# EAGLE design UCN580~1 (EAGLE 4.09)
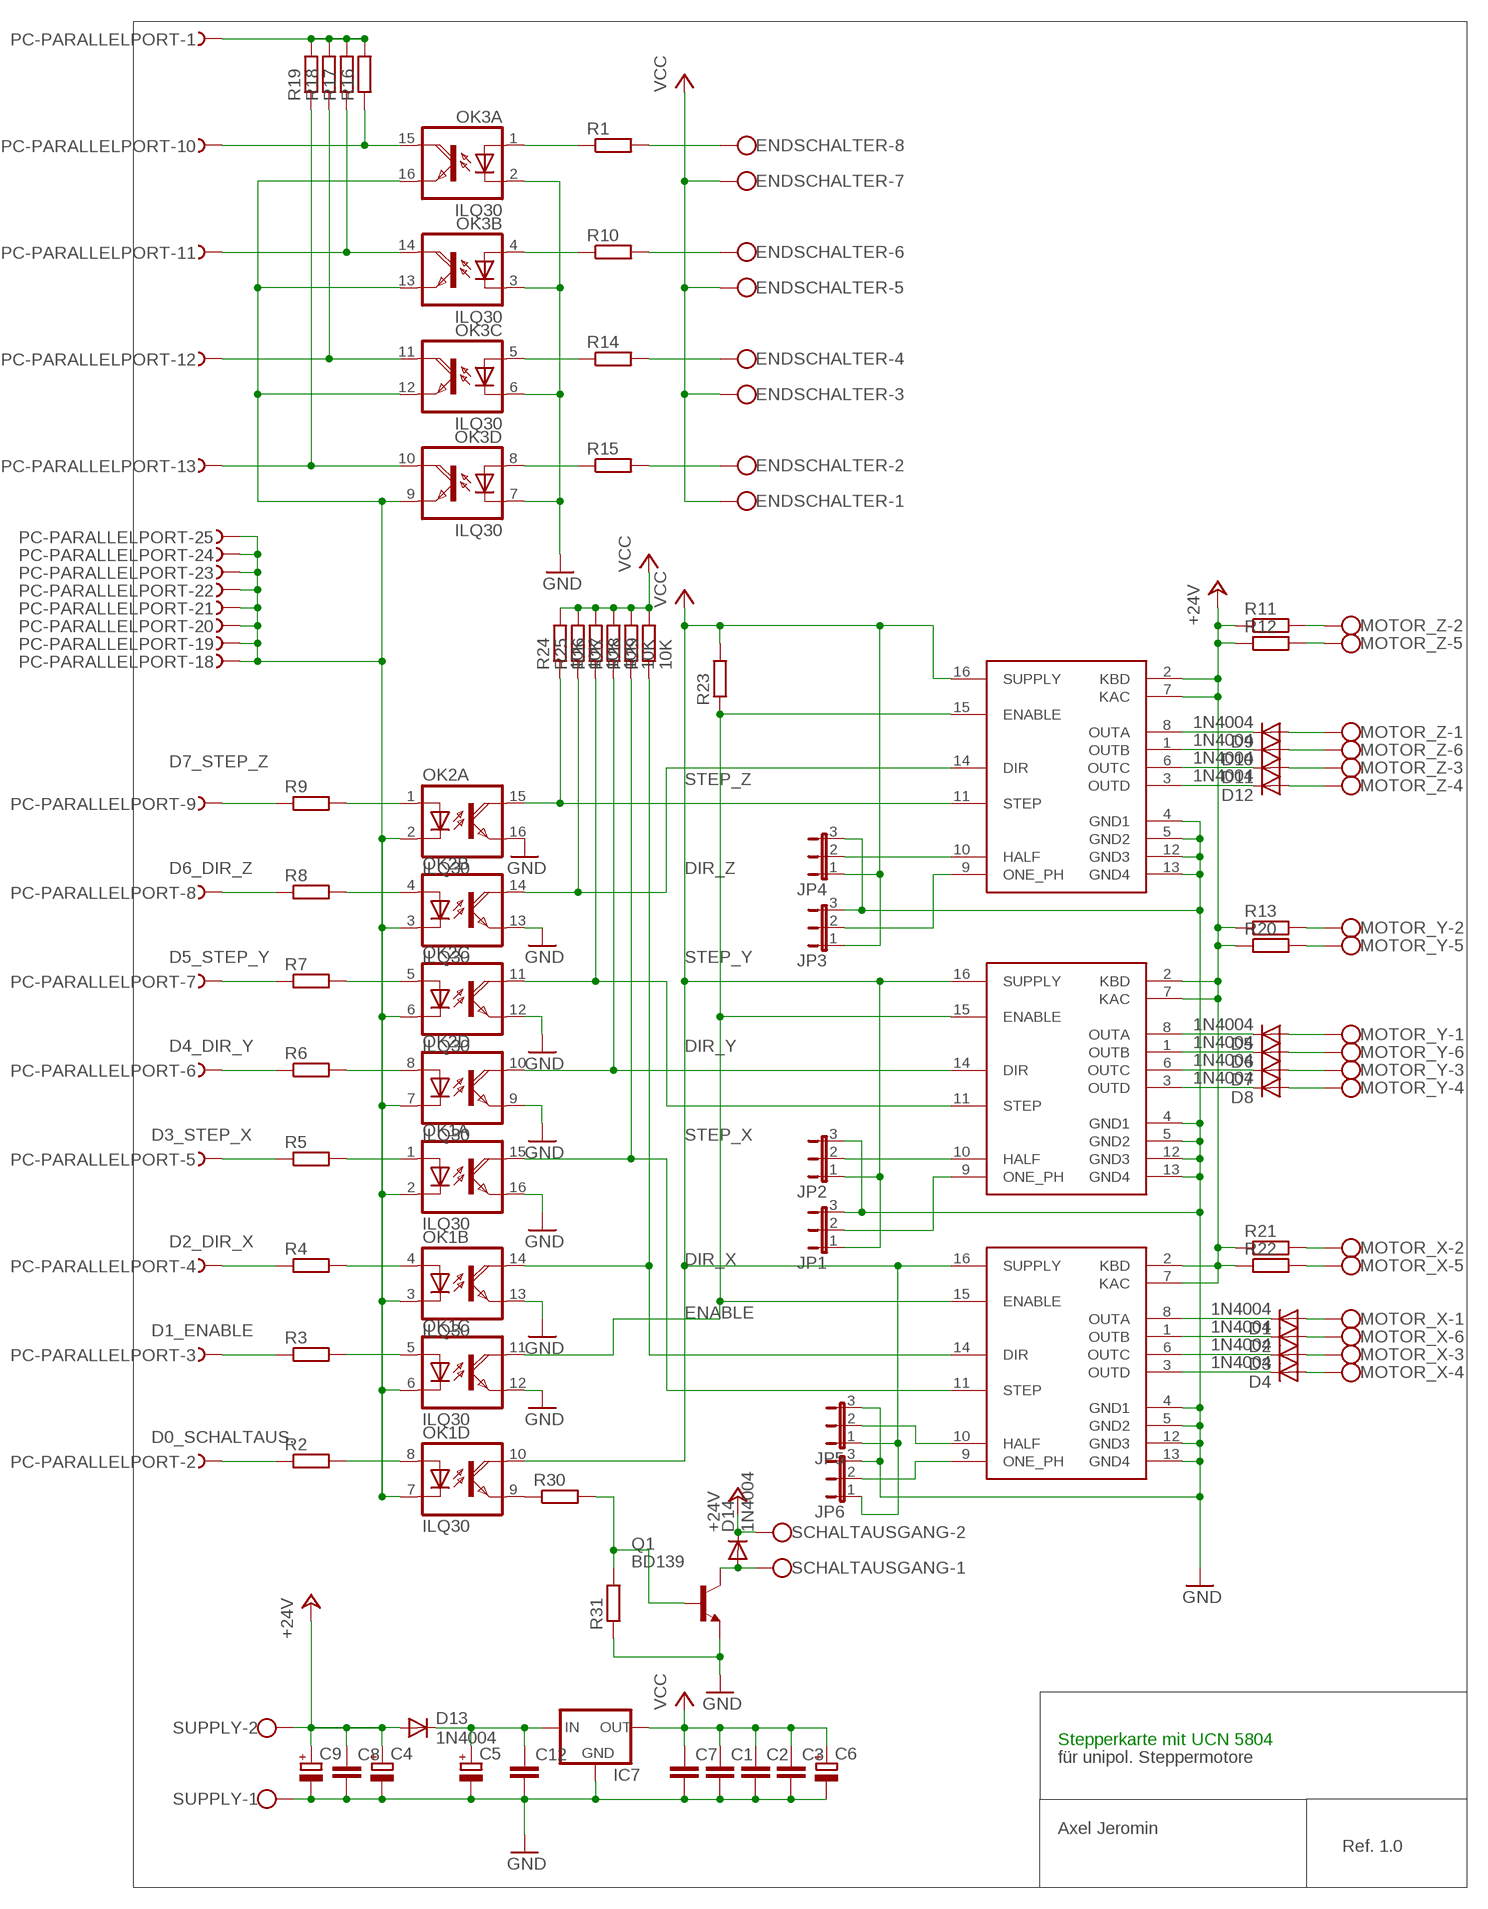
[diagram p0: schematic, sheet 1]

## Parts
C1  C-EU050-025X075  [C050-025X075]
C2  C-EU050-025X075  [C050-025X075]
C3  C-EU050-025X075  [C050-025X075]
C4  CPOL-EUE5-10.5  [E5-10,5]
C5  CPOL-EUE5-10.5  [E5-10,5]
C6  CPOL-EUE5-8.5  [E5-8,5]
C7  C-EU025-030X050  [C025-030X050]
C8  C-EU050-025X075  [C050-025X075]
C9  CPOL-EUE5-8.5  [E5-8,5]
C12  C-EU025-030X050  [C025-030X050]
D1  1N4004  [DO41-10]
D2  1N4004  [DO41-10]
D3  1N4004  [DO41-10]
D4  1N4004  [DO41-10]
D5  1N4004  [DO41-10]
D6  1N4004  [DO41-10]
D7  1N4004  [DO41-10]
D8  1N4004  [DO41-10]
D9  1N4004  [DO41-10]
D10  1N4004  [DO41-10]
D11  1N4004  [DO41-10]
D12  1N4004  [DO41-10]
D13  1N4004  [DO41-10]
D14  1N4004  [DO41-10]
ENDSCHALTER  AK300/8  [AK300/8]
IC7  78XXS  [78XXS]
JP1  JP2E  [JP2]
JP2  JP2E  [JP2]
JP3  JP2E  [JP2]
JP4  JP2E  [JP2]
JP5  JP2E  [JP2]
JP6  JP2E  [JP2]
MOTOR_X  AK300/6  [AK300/6]
MOTOR_Y  AK300/6  [AK300/6]
MOTOR_Z  AK300/6  [AK300/6]
OK1  ILQ30  [DIL16]
OK2  ILQ30  [DIL16]
OK3  ILQ30  [DIL16]
PC-PARALLELPORT  F25HS  [F25H]
Q1  BD139  [TO126]
R1  R-EU_0207/2V  [0207/2V]
R2  R-EU_0204/7  [0204/7]
R3  R-EU_0204/7  [0204/7]
R4  R-EU_0204/7  [0204/7]
R5  R-EU_0204/7  [0204/7]
R6  R-EU_0204/7  [0204/7]
R7  R-EU_0204/5  [0204/5]
R8  R-EU_0204/5  [0204/5]
R9  R-EU_0204/5  [0204/5]
R10  R-EU_0207/2V  [0207/2V]
R11  R-EU_0414/15  [0414/15]
R12  R-EU_0414/15  [0414/15]
R13  R-EU_0414/15  [0414/15]
R14  R-EU_0207/2V  [0207/2V]
R15  R-EU_0207/2V  [0207/2V]
R16  R-EU_0207/15  [0207/15]
R17  R-EU_0207/12  [0207/12]
R18  R-EU_0204/7  [0204/7]
R19  R-EU_0204/5  [0204/5]
R20  R-EU_0414/15  [0414/15]
R21  R-EU_0414/15  [0414/15]
R22  R-EU_0414/15  [0414/15]
R23  R-EU_0204/5  [0204/5]
R24  10K  R-EU_0207/10  [0207/10]
R25  10K  R-EU_0204/7  [0204/7]
R26  10K  R-EU_0207/10  [0207/10]
R27  10K  R-EU_0204/7  [0204/7]
R28  10K  R-EU_0204/7  [0204/7]
R29  10K  R-EU_0204/5  [0204/5]
R30  R-EU_0204/7  [0204/7]
R31  R-EU_0204/5  [0204/5]
SCHALTAUSGANG  AK300/2  [AK300/2]
SUPPLY  AK300/2  [AK300/2]
X-ACHSE  UCN5804  [DIL16]
Y-ACHSE  UCN5804  [DIL16]
Z-ACHSE  UCN5804  [DIL16]

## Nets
+24V: C4.+ C8.1 C9.+ D13.A D14.C R11.1 R12.1 R13.1 R20.1 R21.1 R22.1 SCHALTAUSGANG.2 SUPPLY.2 X-ACHSE.2(KBD) X-ACHSE.7(KAC) Y-ACHSE.2(KBD) Y-ACHSE.7(KAC) Z-ACHSE.2(KBD) Z-ACHSE.7(KAC)
D0_SCHALTAUS.: PC-PARALLELPORT.2 R2.1
D1_ENABLE: PC-PARALLELPORT.3 R3.1
D2_DIR_X: PC-PARALLELPORT.4 R4.1
D3_STEP_X: PC-PARALLELPORT.5 R5.1
D4_DIR_Y: PC-PARALLELPORT.6 R6.1
D5_STEP_Y: PC-PARALLELPORT.7 R7.1
D6_DIR_Z: PC-PARALLELPORT.8 R8.1
D7_STEP_Z: PC-PARALLELPORT.9 R9.1
DIR_X: OK1.14(B:COL) R29.1 X-ACHSE.14(DIR)
DIR_Y: OK2.10(D:COL) R27.1 Y-ACHSE.14(DIR)
DIR_Z: OK2.14(B:COL) R25.1 Z-ACHSE.14(DIR)
ENABLE: OK1.11(C:COL) R23.1 X-ACHSE.15(ENABLE) Y-ACHSE.15(ENABLE) Z-ACHSE.15(ENABLE)
GND: C1.2 C2.2 C3.2 C4.- C5.- C6.- C7.2 C8.2 C9.- C12.2 IC7.GND JP1.3 JP2.3 JP3.3 JP4.3 JP5.3 JP6.3 OK1.12(C:EMI) OK1.13(B:EMI) OK1.16(A:EMI) OK2.9(D:EMI) OK2.12(C:EMI) OK2.13(B:EMI) OK2.16(A:EMI) OK3.2(A:C) OK3.3(B:C) OK3.6(C:C) OK3.7(D:C) Q1.1(E) R31.1 SUPPLY.1 X-ACHSE.4(GND1) X-ACHSE.5(GND2) X-ACHSE.12(GND3) X-ACHSE.13(GND4) Y-ACHSE.4(GND1) Y-ACHSE.5(GND2) Y-ACHSE.12(GND3) Y-ACHSE.13(GND4) Z-ACHSE.4(GND1) Z-ACHSE.5(GND2) Z-ACHSE.12(GND3) Z-ACHSE.13(GND4)
LIMIT_1: OK3.10(D:COL) PC-PARALLELPORT.13 R19.1
LIMIT_2: OK3.11(C:COL) PC-PARALLELPORT.12 R18.1
LIMIT_3: OK3.14(B:COL) PC-PARALLELPORT.11 R17.1
LIMIT_4: OK3.15(A:COL) PC-PARALLELPORT.10 R16.1
N$1: OK1.2(A:C) OK1.3(B:C) OK1.6(C:C) OK1.7(D:C) OK2.2(A:C) OK2.3(B:C) OK2.6(C:C) OK2.7(D:C) OK3.9(D:EMI) OK3.12(C:EMI) OK3.13(B:EMI) OK3.16(A:EMI) PC-PARALLELPORT.18 PC-PARALLELPORT.19 PC-PARALLELPORT.20 PC-PARALLELPORT.21 PC-PARALLELPORT.22 PC-PARALLELPORT.23 PC-PARALLELPORT.24 PC-PARALLELPORT.25
N$2: C5.+ C12.1 D13.C IC7.IN
N$3: D9.C Z-ACHSE.8(OUTA)
N$4: D10.C Z-ACHSE.1(OUTB)
N$5: OK2.4(B:A) R8.2
N$6: OK1.8(D:A) R2.2
N$7: OK1.5(C:A) R3.2
N$8: D11.C Z-ACHSE.6(OUTC)
N$9: D12.C Z-ACHSE.3(OUTD)
N$10: PC-PARALLELPORT.1 R16.2 R17.2 R18.2 R19.2
N$11: D5.C Y-ACHSE.8(OUTA)
N$12: D6.C Y-ACHSE.1(OUTB)
N$13: OK2.1(A:A) R9.2
N$14: OK1.4(B:A) R4.2
N$15: OK1.1(A:A) R5.2
N$16: OK2.8(D:A) R6.2
N$17: OK2.5(C:A) R7.2
N$18: D7.C Y-ACHSE.6(OUTC)
N$19: D8.C Y-ACHSE.3(OUTD)
N$20: D1.C X-ACHSE.8(OUTA)
N$21: D2.C X-ACHSE.1(OUTB)
N$22: D3.C X-ACHSE.6(OUTC)
N$23: D4.C X-ACHSE.3(OUTD)
N$24: MOTOR_Z.2 R11.2
N$25: MOTOR_Z.5 R12.2
N$26: MOTOR_X.5 R22.2
N$27: D1.A MOTOR_X.1
N$28: MOTOR_Y.2 R13.2
N$29: MOTOR_Y.5 R20.2
N$30: D2.A MOTOR_X.6
N$31: D3.A MOTOR_X.3
N$32: D4.A MOTOR_X.4
N$33: D5.A MOTOR_Y.1
N$34: MOTOR_X.2 R21.2
N$35: OK3.1(A:A) R1.1
N$36: D6.A MOTOR_Y.6
N$37: OK3.4(B:A) R10.1
N$38: D7.A MOTOR_Y.3
N$39: ENDSCHALTER.8 R1.2
N$40: ENDSCHALTER.6 R10.2
N$41: ENDSCHALTER.4 R14.2
N$42: ENDSCHALTER.2 R15.2
N$43: OK3.5(C:A) R14.1
N$44: D8.A MOTOR_Y.4
N$45: OK3.8(D:A) R15.1
N$46: D9.A MOTOR_Z.1
N$47: D10.A MOTOR_Z.6
N$48: D11.A MOTOR_Z.3
N$49: D12.A MOTOR_Z.4
N$50: OK1.9(D:EMI) R30.1
N$51: JP6.2 X-ACHSE.9(ONE_PH)
N$52: JP5.2 X-ACHSE.10(HALF)
N$53: JP1.2 Y-ACHSE.9(ONE_PH)
N$54: JP2.2 Y-ACHSE.10(HALF)
N$55: JP3.2 Z-ACHSE.9(ONE_PH)
N$56: JP4.2 Z-ACHSE.10(HALF)
N$57: Q1.3(B) R30.2 R31.2
N$58: D14.A Q1.2(C) SCHALTAUSGANG.1
STEP_X: OK1.15(A:COL) R28.1 X-ACHSE.11(STEP)
STEP_Y: OK2.11(C:COL) R26.1 Y-ACHSE.11(STEP)
STEP_Z: OK2.15(A:COL) R24.1 Z-ACHSE.11(STEP)
VCC: C1.1 C2.1 C3.1 C6.+ C7.1 ENDSCHALTER.1 ENDSCHALTER.3 ENDSCHALTER.5 ENDSCHALTER.7 IC7.OUT JP1.1 JP2.1 JP3.1 JP4.1 JP5.1 JP6.1 OK1.10(D:COL) R23.2 R24.2 R25.2 R26.2 R27.2 R28.2 R29.2 X-ACHSE.16(SUPPLY) Y-ACHSE.16(SUPPLY) Z-ACHSE.16(SUPPLY)
Unconnected: PC-PARALLELPORT.14 PC-PARALLELPORT.15 PC-PARALLELPORT.16 PC-PARALLELPORT.17

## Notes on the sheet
- Stepperkarte mit UCN 5804
- für unipol. Steppermotore
- Axel Jeromin
- Ref. 1.0

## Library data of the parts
C1-C3 C7 C8 C12 = rcl:C-EU: CAPACITOR, European symbol
C4-C6 C9 = rcl:CPOL-EU: POLARIZED CAPACITOR, European symbol
D1-D14 = diode:1N4004: DIODE
ENDSCHALTER = con-ptr500:AK300/8: CONNECTOR
IC7 = v-reg:78XXS: VOLTAGE REGULATOR
JP1-JP6 = jumper:JP2E: JUMPER
MOTOR_X MOTOR_Y MOTOR_Z = con-ptr500:AK300/6: CONNECTOR
OK1-OK3 = optocoupler:ILQ30: SIEMENS OPTO COUPLER
PC-PARALLELPORT = con-subd:F25?S: SUB-D
Q1 = transistor-npn:BD139*: NPN Transistor
R1-R31 = rcl:R-EU_: RESISTOR, European symbol
SCHALTAUSGANG SUPPLY = con-ptr500:AK300/2: CONNECTOR
X-ACHSE Y-ACHSE Z-ACHSE = uln-udn:UCN5804: Stepper

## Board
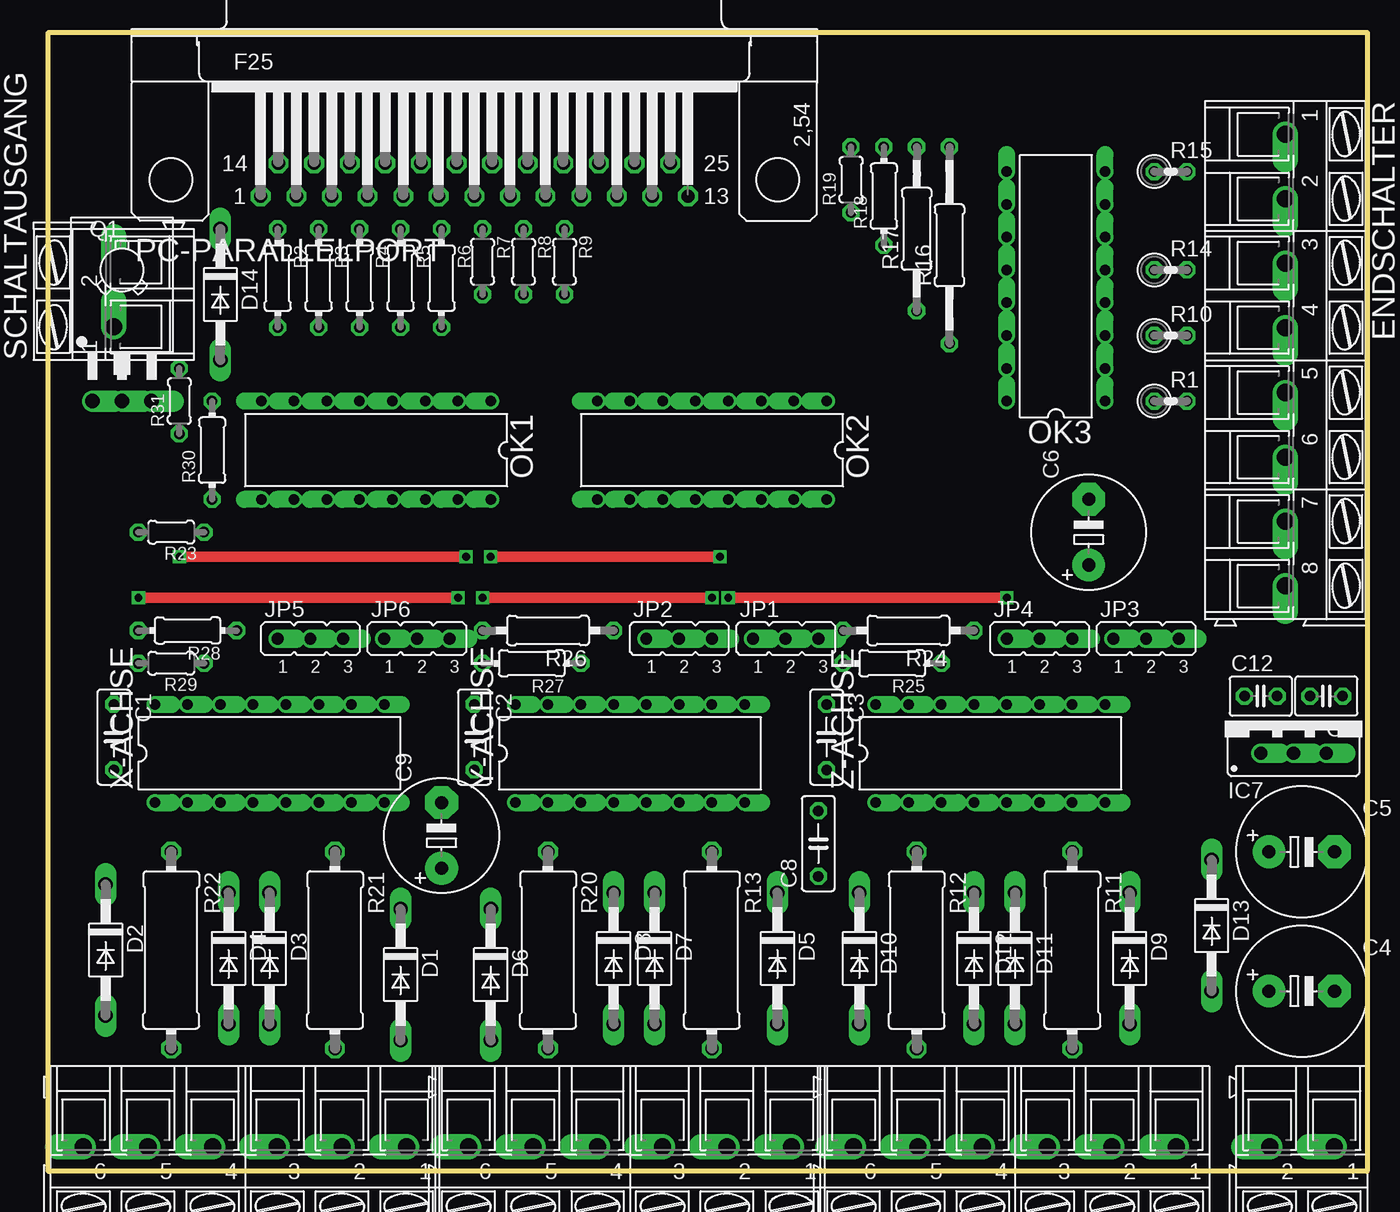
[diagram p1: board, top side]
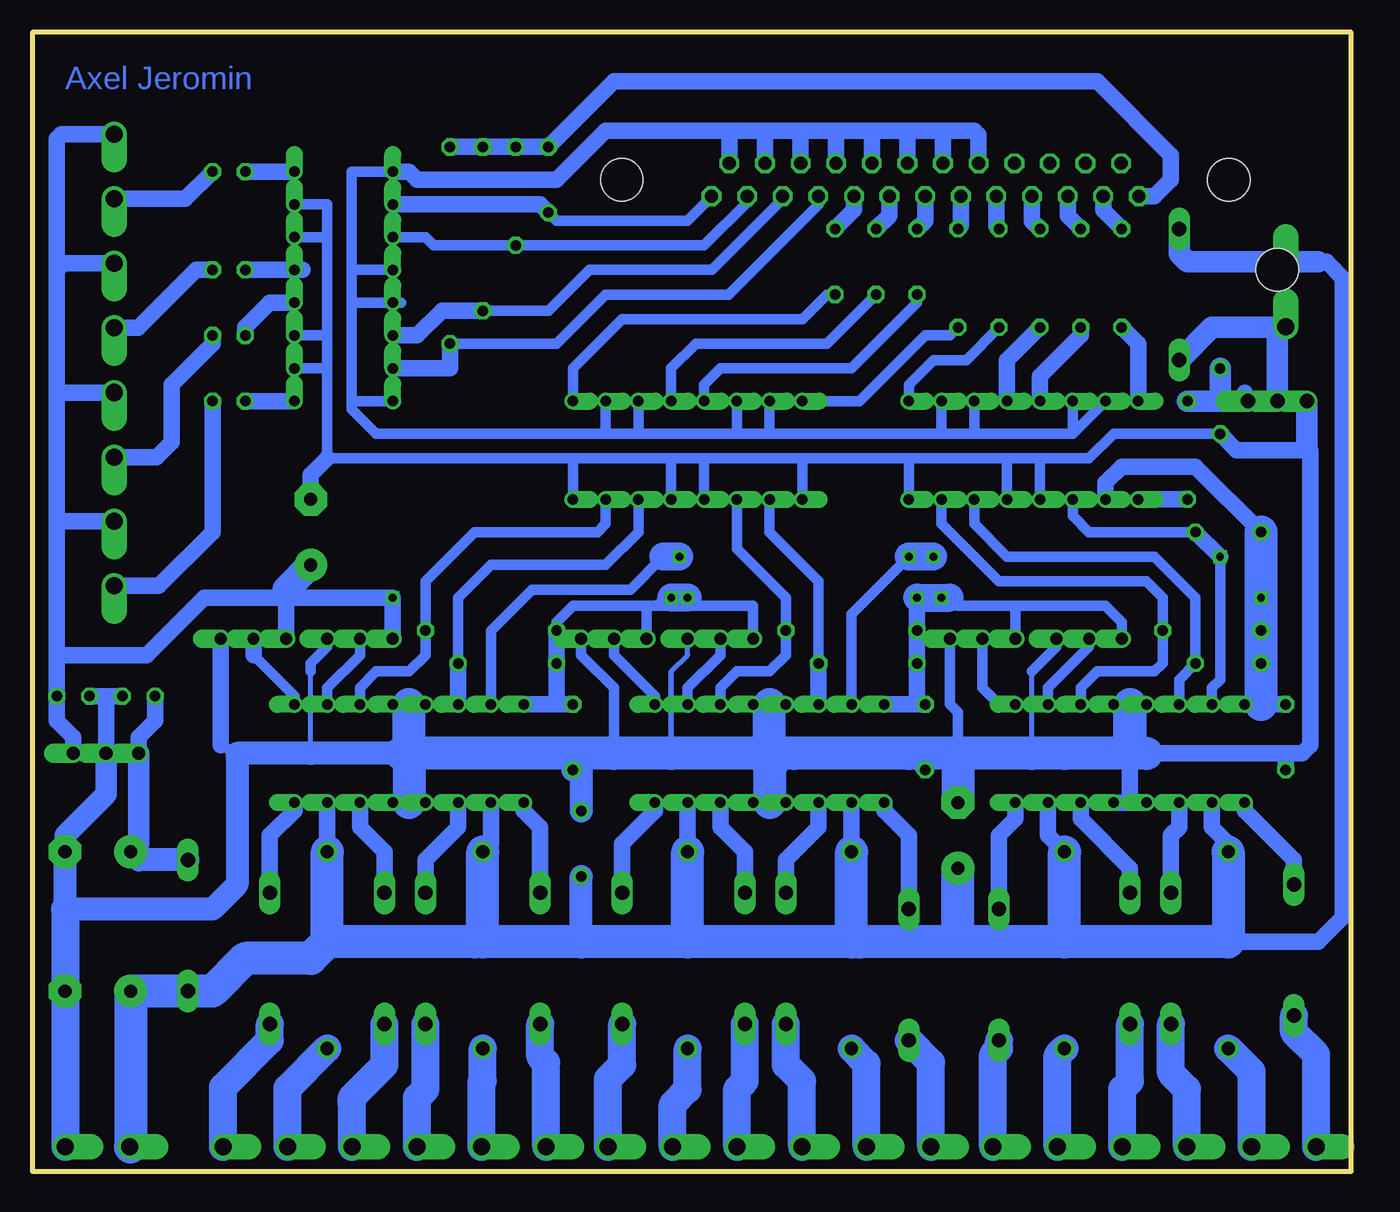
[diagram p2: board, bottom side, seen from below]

Size 102.23 x 88.27 mm. Coordinates in mm from the lower left corner, seen from the top.
Outline: 0,0 0,88.27 102.23,88.27 102.23,0 0,0
Copper layers used: Top, Bottom

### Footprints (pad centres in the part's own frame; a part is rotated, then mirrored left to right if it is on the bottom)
C050-025X075 = drill 0.813 octagon: 1 -2.54,0; 2 2.54,0
E5-10,5 = drill 1.016 pad 2.54 round: + -2.54,0 | drill 1.016 pad 2.54 octagon: - 2.54,0
E5-8,5 = drill 1.016 pad 2.54 round: + -2.54,0 | drill 1.016 pad 2.54 octagon: - 2.54,0
C025-030X050 = drill 0.813 octagon: 1 -1.27,0; 2 1.27,0
DO41-10 = drill 1.118 long: A 5.08,0; C -5.08,0
AK300/8 = drill 1.321 offset: 1 -17.501,0; 2 -12.497,0; 3 -7.518,0; 4 -2.515,0; 5 2.515,0; 6 7.518,0; 7 12.497,0; 8 17.501,0
78XXS = drill 1.016 offset: GND 0,-2.54; IN -2.54,-2.54; OUT 2.54,-2.54
JP2 = drill 0.914 offset: 1 -2.54,0; 2 0,0; 3 2.54,0
AK300/6 = drill 1.321 offset: 1 -12.522,0; 2 -7.518,0; 3 -2.515,0; 4 2.515,0; 5 7.518,0; 6 12.522,0
DIL16 = drill 0.813 offset: 1 -8.89,-3.81; 2 -6.35,-3.81; 3 -3.81,-3.81; 4 -1.27,-3.81; 5 1.27,-3.81; 6 3.81,-3.81; 7 6.35,-3.81; 8 8.89,-3.81; 9 8.89,3.81; 10 6.35,3.81; 11 3.81,3.81; 12 1.27,3.81; 13 -1.27,3.81; 14 -3.81,3.81; 15 -6.35,3.81; 16 -8.89,3.81
F25H = drill 1.016 octagon: 1 -16.561,-1.27; 2 -13.792,-1.27; 3 -11.049,-1.27; 4 -8.28,-1.27; 5 -5.512,-1.27; 6 -2.769,-1.27; 7 0,-1.27; 8 2.769,-1.27; 9 5.512,-1.27; 10 8.28,-1.27; 11 11.049,-1.27; 12 13.792,-1.27; 13 16.561,-1.27; 14 -15.189,1.27; 15 -12.421,1.27; 16 -9.652,1.27; 17 -6.909,1.27; 18 -4.14,1.27; 19 -1.372,1.27; 20 1.372,1.27; 21 4.14,1.27; 22 6.909,1.27; 23 9.652,1.27; 24 12.421,1.27; 25 15.189,1.27 | hole 3.302: -23.52,0; 23.52,0
TO126 = drill 1.118 offset: 1 -2.286,-5.08; 2 0,-5.08; 3 2.286,-5.08 | hole 3.302: 0,5.08
0207/2V = drill 0.813 octagon: 1 -1.27,0; 2 1.27,0
0204/7 = drill 0.813 octagon: 1 -3.81,0; 2 3.81,0
0204/5 = drill 0.813 octagon: 1 -2.54,0; 2 2.54,0
0414/15 = drill 1.016 octagon: 1 -7.62,0; 2 7.62,0
0207/15 = drill 0.813 octagon: 1 -7.62,0; 2 7.62,0
0207/12 = drill 0.813 octagon: 1 -6.35,0; 2 6.35,0
0207/10 = drill 0.813 octagon: 1 -5.08,0; 2 5.08,0
AK300/2 = drill 1.321 offset: 1 -2.515,0; 2 2.489,0

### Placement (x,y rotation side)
C1  5.08,33.66 270 top
C2  33.02,33.66 270 top
C3  60.32,33.66 270 top
C4  97.16,13.97 0 top
C5  97.16,24.77 0 top
C6  80.65,49.53 90 top
C7  99.06,36.83 180 top
C8  59.69,25.4 90 top
C9  30.48,26.04 90 top
C12  93.98,36.83 0 top
D1  27.31,15.24 270 top
D2  4.45,17.14 270 top
D3  17.15,16.51 270 top
D4  13.97,16.51 270 top
D5  56.52,16.51 270 top
D6  34.29,15.24 270 top
D7  46.99,16.51 270 top
D8  43.81,16.51 270 top
D9  83.82,16.51 270 top
D10  62.86,16.51 270 top
D11  74.93,16.51 270 top
D12  71.76,16.51 270 top
D13  90.17,19.05 270 top
D14  13.33,67.94 270 top
ENDSCHALTER  95.89,62.87 270 top
IC7  96.52,34.92 0 top
JP1  57.15,41.27 0 top
JP2  48.89,41.27 0 top
JP3  85.09,41.27 0 top
JP4  76.84,41.27 0 top
JP5  20.32,41.27 0 top
JP6  28.58,41.27 0 top
MOTOR_X  15.24,1.91 180 top
MOTOR_Y  45.09,1.91 180 top
MOTOR_Z  74.93,1.91 180 top
OK1  25.4,55.88 180 top
OK2  51.43,55.88 180 top
OK3  78.11,68.58 90 top
PC-PARALLELPORT  33.02,76.83 0 top
Q1  5.71,64.77 0 top
R1  87,59.69 0 top
R2  17.78,69.22 270 top
R3  20.96,69.22 270 top
R4  24.13,69.22 270 top
R5  27.31,69.22 270 top
R6  30.48,69.22 270 top
R7  33.66,70.48 270 top
R8  36.83,70.48 270 top
R9  40,70.48 270 top
R10  87,64.77 0 top
R11  79.38,17.14 270 top
R12  67.31,17.14 270 top
R13  51.43,17.14 270 top
R14  87,69.85 0 top
R15  87,77.47 0 top
R16  69.85,71.75 90 top
R17  67.31,73.03 90 top
R18  64.77,75.56 90 top
R19  62.23,76.83 90 top
R20  38.73,17.14 270 top
R21  22.23,17.14 270 top
R22  9.53,17.14 270 top
R23  9.53,49.53 180 top
R24  66.68,41.91 180 top
R25  65.41,39.37 180 top
R26  38.73,41.91 180 top
R27  37.46,39.37 180 top
R28  10.79,41.91 180 top
R29  9.53,39.37 180 top
R30  12.7,55.88 90 top
R31  10.16,59.69 90 top
SCHALTAUSGANG  5.08,67.94 90 top
SUPPLY  97.16,1.91 180 top
X-ACHSE  17.15,32.38 0 top
Y-ACHSE  45.09,32.38 0 top
Z-ACHSE  73.03,32.38 0 top

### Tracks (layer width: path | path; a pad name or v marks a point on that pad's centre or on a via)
+24V
  Bottom 0.305: 30.48,18.41 38.1,18.41 38.1,17.78 | SCHALTAUSGANG.2 2.59,70.43 2.54,70.48
  Bottom 0.813: 94.62,1.91 SUPPLY.2
  Bottom 1.27: Z-ACHSE.7 79.38,25.4 78.74,24.77 R11.1 | R20.1 Y-ACHSE.2 | R13.1 Y-ACHSE.7 | Z-ACHSE.2 66.68,25.4 R12.1 | 9.53,25.4 R22.1 | R21.1 23.5,26.04 X-ACHSE.7 | X-ACHSE.2 10.79,26.67 9.53,25.4 | 9.53,25.4 9.53,18.41 8.89,17.78 2.54,17.78 0.64,19.68 0.64,69.22 1.91,70.48 2.54,70.48
  Bottom 1.676: 2.54,70.48 12.7,70.48 13.33,71.12 D14.C
  Bottom 1.778: C8.1 59.69,17.78 67.95,17.78
  Bottom 2.184: C4.+ 94.67,13.92
  Bottom 2.54: 79.38,17.78 R11.1 | 22.23,17.78 9.53,17.78 R22.1 | 22.23,17.78 38.1,17.78 38.73,17.78 | 38.73,17.78 51.43,17.78 | 51.43,17.78 59.69,17.78 67.31,17.78 | 67.31,17.78 67.95,17.78 79.38,17.78 | 22.23,17.78 R21.1 | 38.73,17.78 R20.1 | 51.43,17.78 R13.1 | 67.31,17.78 R12.1 | 79.38,17.78 80.65,16.51 85.73,16.51 88.27,13.97 D13.A C4.+ 94.62,1.91 | 30.48,18.41 C9.+
D0_SCHALTAUS.
  Bottom 1.27: PC-PARALLELPORT.2 19.23,74.47 R2.1
D1_ENABLE
  Bottom 1.27: PC-PARALLELPORT.3 21.97,74.04 R3.1
D2_DIR_X
  Bottom 1.27: PC-PARALLELPORT.4 24.74,73.64 R4.1
D3_STEP_X
  Bottom 1.27: PC-PARALLELPORT.5 27.51,73.23 R5.1
D4_DIR_Y
  Bottom 1.27: PC-PARALLELPORT.6 30.25,73.25 R6.1
D5_STEP_Y
  Bottom 1.27: PC-PARALLELPORT.7 33.02,73.66 R7.1
D6_DIR_Z
  Bottom 1.27: PC-PARALLELPORT.8 35.79,74.07 R8.1
D7_STEP_Z
  Bottom 1.27: PC-PARALLELPORT.9 38.53,74.5 R9.1
DIR_X
  Bottom 0.813: OK1.14 29.21,50.16 26.67,47.62 15.24,47.62 12.06,44.45 R29.1 13.33,38.1 X-ACHSE.14
DIR_Y
  Bottom 0.813: R27.1 41.27,45.72 45.09,49.53 OK2.10
  Bottom 1.27: Y-ACHSE.14 R27.1
DIR_Z
  Bottom 0.813: R25.1 69.22,44.45 66.68,46.99 57.78,46.99 55.24,49.53 OK2.14
  Bottom 1.27: R25.1 Z-ACHSE.14
ENABLE  (via drill 0.61)
  Top 0.813: v10.16,47.62 v32.38,47.62 | v34.29,47.62 v52.07,47.62
  Bottom 0.813: Z-ACHSE.15 66.68,41.91 63.5,45.09 55.88,45.09 53.34,47.62 | R23.1 20.32,49.53 21.59,50.8 OK1.11 | X-ACHSE.15 10.79,37.47 10.16,38.1 v10.16,47.62 | v34.29,47.62 38.73,43.18 Y-ACHSE.15
  Bottom 1.27: v10.16,47.62 R23.1
  Bottom 2.184: v32.38,47.62 v34.29,47.62 | v52.07,47.62 53.34,47.62
GND
  Bottom 0.254: 45.09,31.11 43.81,31.11 43.81,31.75 43.18,32.38 | 73.03,32.38 73.03,34.92 Z-ACHSE.12
  Bottom 0.406: 80.65,32.38 80.65,38.73 | JP2.3 51.43,40.01 52.7,38.73 | 52.7,38.73 52.7,33.02 | 22.23,32.38 18.42,32.38 17.15,33.66 17.15,34.92 X-ACHSE.12 | 29.85,33.02 24.77,33.02 | 52.7,32.38 52.7,38.73 | 24.77,32.38 24.77,38.73
  Bottom 0.813: OK1.12 24.13,55.24 26.67,55.24 | 26.67,55.24 OK1.13 | 34.29,55.24 26.67,55.24 | 34.29,55.24 OK1.16 | 42.54,55.24 34.29,55.24 | 52.7,55.24 50.16,55.24 | 50.16,55.24 OK2.12 | 50.16,55.24 42.54,55.24 | 42.54,55.24 OK2.9 | 42.54,55.24 26.67,55.24 | 30.48,32.38 43.81,32.38 44.45,33.02 44.45,35.56 Y-ACHSE.13 | OK3.7 79.38,74.93 79.38,72.39 | 79.38,72.39 OK3.6 | 79.38,64.77 79.38,72.39 | 79.38,64.77 OK3.3 | 79.38,62.23 79.38,64.77 | 79.38,62.23 OK3.2 | 79.38,55.24 79.38,62.23 | 73.66,32.38 73.66,35.56 Z-ACHSE.12 | 86.36,32.38 87.63,33.02 | JP4.3 79.38,40.64 80.65,39.37 80.65,38.73 | 30.48,32.38 29.85,33.02 | 52.7,55.24 OK2.13 | 60.32,55.24 52.7,55.24 | 60.32,55.24 OK2.16 | 79.38,55.24 60.32,55.24 | JP5.3 22.86,40.64 24.77,38.73 | 79.38,55.24 20.32,55.24 18.42,57.15 R31.1 | JP6.3 31.12,36.2 30.48,35.56 30.48,32.38 | 57.15,32.38 57.15,37.47 59.69,40.01 JP1.3
  Bottom 1.27: X-ACHSE.12 17.15,36.2 X-ACHSE.13 16.51,36.2 16.51,33.02 15.88,33.02 15.88,32.38 5.08,32.38 C1.2 | Y-ACHSE.12 45.09,36.2 Y-ACHSE.13 | Y-ACHSE.4 45.09,28.57 Y-ACHSE.5 | Z-ACHSE.12 73.03,36.2 Z-ACHSE.13 | Z-ACHSE.4 73.03,28.57 Z-ACHSE.5 | 60.32,32.38 C3.2 | 52.7,32.38 45.09,32.38 45.09,31.11 | 34.29,32.38 C2.2 | IC7.GND 96.52,36.83 C12.2 C7.2 | 87.63,33.02 JP3.3 | 29.85,33.02 30.48,33.02 | 79.38,55.24 80.65,53.98 C6.- | 17.15,28.57 X-ACHSE.4 | 17.15,28.57 17.15,32.38 3.81,32.38 3.17,33.02 3.17,55.88 | 17.15,28.57 X-ACHSE.5 | R31.1 8.89,55.88 3.17,55.88 | 3.17,55.88 3.43,56.13
  Bottom 1.676: IC7.GND 96.52,29.21 99.7,26.04 C5.- | 3.43,56.13 Q1.1
  Bottom 1.778: C5.- 99.7,20.32 88.27,20.32 86.36,22.23 86.36,32.38 80.65,32.38 73.66,32.38 | C8.2 59.69,31.11 C3.2
  Bottom 2.184: SUPPLY.1 99.67,13.95 C4.- 99.7,20.32
  Bottom 2.54: 15.88,32.38 17.15,32.38 22.23,32.38 24.77,32.38 30.48,32.38 | 30.48,32.38 34.29,32.38 43.18,32.38 52.7,32.38 57.15,32.38 60.32,32.38 73.03,32.38 | 73.03,32.38 73.66,32.38 | 17.15,33.66 17.15,36.2 | 45.09,28.57 45.09,31.11 45.09,36.2 | 73.03,32.38 73.03,28.57 | 73.03,32.38 73.03,36.2 | 30.48,32.38 C9.-
LIMIT_1
  Bottom 0.813: PC-PARALLELPORT.13 49.58,75.51 51.43,73.66 61.59,73.66 62.86,74.93
  Bottom 1.27: OK3.10 62.86,74.93 R19.1
LIMIT_2
  Bottom 0.813: PC-PARALLELPORT.12 46.81,75.11 50.16,71.75 R18.1 71.12,71.75 71.76,72.39 OK3.11
LIMIT_3
  Bottom 0.813: PC-PARALLELPORT.11 44.07,75.31 49.53,69.85 59.05,69.85 62.23,66.67 R17.1
  Bottom 1.27: OK3.14 72.39,64.77 70.48,66.67 R17.1
LIMIT_4
  Bottom 0.813: PC-PARALLELPORT.10 41.3,74.91 48.26,67.94 57.78,67.94 61.59,64.14 R16.1
  Bottom 1.27: OK3.15 69.85,62.23 R16.1
N$1
  Bottom 0.813: 21.59,57.15 OK1.6 | 21.59,57.15 29.21,57.15 | 29.21,57.15 OK1.3 | 29.21,57.15 31.75,57.15 | 31.75,57.15 OK1.2 | 31.75,57.15 45.09,57.15 | 45.09,57.15 OK2.7 | 45.09,57.15 47.62,57.15 | 47.62,57.15 OK2.6 | 47.62,57.15 55.24,57.15 | 55.24,57.15 OK2.3 | 55.24,57.15 57.78,57.15 | OK3.9 77.47,77.47 77.47,69.85 | 77.47,69.85 OK3.12 | 77.47,67.31 77.47,69.85 | 77.47,67.31 OK3.13 73.66,67.31 | 77.47,59.69 77.47,67.31 | 29.21,80.64 28.88,80.31 | 31.75,80.64 31.65,80.54 | 34.29,80.64 34.39,80.54 | 37.46,80.64 37.16,80.34 | 40,80.64 39.93,80.57 | 42.54,80.64 42.67,80.52 | 45.09,80.64 45.44,80.29 | 48.26,80.64 48.21,80.59 | 57.78,57.15 OK2.2 | 57.78,57.15 75.57,57.15 77.47,59.05 77.47,59.69 | 77.47,59.69 OK3.16 | OK1.7 21.59,57.15
  Bottom 1.27: 28.88,80.31 PC-PARALLELPORT.18 | 29.21,80.64 31.75,80.64 34.29,80.64 37.46,80.64 40,80.64 42.54,80.64 45.09,80.64 48.26,80.64 57.78,80.64 61.59,76.83 72.39,76.83 73.03,77.47 OK3.9 | 31.65,80.54 PC-PARALLELPORT.19 | 34.39,80.54 PC-PARALLELPORT.20 | 37.16,80.34 PC-PARALLELPORT.21 | 39.93,80.57 PC-PARALLELPORT.22 | 42.67,80.52 PC-PARALLELPORT.23 | 45.44,80.29 PC-PARALLELPORT.24 | 48.21,80.59 PC-PARALLELPORT.25
N$2
  Bottom 1.27: C5.+ 93.98,25.4 | C12.1 92.71,34.92 93.98,33.66 IC7.IN
  Bottom 1.676: 93.98,25.4 IC7.IN
  Bottom 1.778: D13.C 93.98,24.13 C5.+
N$3
  Bottom 1.27: Z-ACHSE.8 81.92,27.94 83.82,26.04 D9.C
N$4
  Bottom 1.27: Z-ACHSE.1 64.14,27.94 62.86,26.67 D10.C
N$5
  Bottom 0.813: R8.2 40.64,64.14 50.8,64.14 52.7,62.23 OK2.4
N$6
  Bottom 1.27: R2.2 16.51,64.14 OK1.8
N$7
  Bottom 1.27: R3.2 20.96,64.77 24.13,61.59 OK1.5
N$8
  Bottom 1.27: Z-ACHSE.6 76.84,26.67 74.93,24.77 D11.C
N$9
  Bottom 1.27: Z-ACHSE.3 69.22,26.67 71.76,24.13 D12.C
N$10
  Bottom 1.27: PC-PARALLELPORT.1 15.24,75.56 13.97,76.83 13.97,78.74 19.69,84.45 57.15,84.45 R19.2 R18.2 R17.2 R16.2
N$11
  Bottom 1.27: Y-ACHSE.8 53.98,27.94 56.52,25.4 D5.C
N$12
  Bottom 1.27: Y-ACHSE.1 36.2,27.94 34.29,26.04 D6.C
N$13
  Bottom 0.813: OK2.1 60.32,62.23 56.52,66.04 42.54,66.04 40.64,67.94 R9.2
N$14
  Bottom 1.27: R4.2 26.67,62.87 OK1.4
N$15
  Bottom 0.813: R5.2 29.85,62.87 32.38,62.87 34.29,60.96 OK1.1
N$16
  Bottom 0.813: R6.2 31.12,64.77 33.02,64.77 38.1,59.69 OK2.8
N$17
  Bottom 0.813: R7.2 33.66,67.31 38.73,62.23 48.89,62.23 50.16,60.96 OK2.5
N$18
  Bottom 1.27: Y-ACHSE.6 48.89,26.67 46.99,24.77 D7.C 46.99,20.95
N$19
  Bottom 1.27: Y-ACHSE.3 41.27,26.67 43.81,24.13 D8.C
N$20
  Bottom 1.27: X-ACHSE.8 26.04,27.3 27.31,26.04 D1.C
N$21
  Bottom 1.27: D2.C 4.45,24.13 8.26,27.94 X-ACHSE.1
N$22
  Bottom 1.27: D3.C 17.15,23.5 20.96,27.3 X-ACHSE.6
N$23
  Bottom 1.27: D4.C 13.97,26.04 13.33,26.67 X-ACHSE.3
N$24
  Bottom 2.184: MOTOR_Z.2 82.45,6.45 R11.2
N$25
  Bottom 2.184: MOTOR_Z.5 67.41,6.88 67.31,6.99 R12.2
N$26
  Bottom 2.184: MOTOR_X.5 7.72,7.72 R22.2
N$27
  Bottom 2.184: MOTOR_X.1 27.76,9.07 27.31,9.53 D1.A
N$28
  Bottom 2.184: MOTOR_Y.2 52.6,5.18 51.43,6.35 R13.2
N$29
  Bottom 2.184: MOTOR_Y.5 37.57,8.36 R20.2
N$30
  Bottom 2.184: MOTOR_X.6 2.72,9.07 4.45,10.79 D2.A
N$31
  Bottom 2.184: MOTOR_X.3 17.76,6.38 17.15,6.99 D3.A
N$32
  Bottom 2.184: MOTOR_X.4 12.72,6.38 13.97,7.62 D4.A
N$33
  Bottom 2.184: MOTOR_Y.1 57.61,7.16 56.52,8.26 D5.A
N$34
  Bottom 2.184: MOTOR_X.2 22.76,8.99 R21.2
N$35
  Bottom 1.27: OK3.1 R1.1
N$36
  Bottom 2.184: MOTOR_Y.6 32.56,8.43 D6.A
N$37
  Bottom 1.27: OK3.4 83.82,67.31 85.73,65.41 R10.1
N$38
  Bottom 2.184: MOTOR_Y.3 47.6,6.38 46.99,6.99 D7.A
N$39
  Bottom 1.27: ENDSCHALTER.8 92.43,45.36 88.27,49.53 R1.2
N$40
  Bottom 1.27: ENDSCHALTER.6 92.61,55.35 91.44,56.52 91.44,60.96 88.27,64.14 R10.2
N$41
  Bottom 1.27: ENDSCHALTER.4 94.01,65.38 89.54,69.85 R14.2
N$42
  Bottom 1.27: ENDSCHALTER.2 90.37,75.36 R15.2
N$43
  Bottom 1.27: R14.1 OK3.5 81.28,69.85
N$44
  Bottom 2.184: MOTOR_Y.4 42.57,7.01 43.81,8.26 D8.A
N$45
  Bottom 1.27: OK3.8 R15.1
N$46
  Bottom 2.184: MOTOR_Z.1 87.45,6.53 83.82,10.16 D9.A
N$47
  Bottom 2.184: MOTOR_Z.6 62.41,8.43 62.86,8.89 D10.A
N$48
  Bottom 2.184: MOTOR_Z.3 77.45,5.11 77.47,5.08 77.47,5.71 74.93,8.26 D11.A
N$49
  Bottom 2.184: MOTOR_Z.4 72.42,5.74 72.39,5.71 71.76,6.35 D12.A
N$50
  Bottom 1.27: R30.1 OK1.9
N$51
  Bottom 0.813: X-ACHSE.9 27.31,36.2 28.58,37.47 JP6.2
N$52
  Bottom 0.813: X-ACHSE.10 23.5,37.47 20.32,40.64 JP5.2
N$53
  Bottom 0.813: JP1.2 57.15,40.01 53.98,36.83 Y-ACHSE.9
N$54
  Bottom 0.813: Y-ACHSE.10 51.43,37.47 48.89,40.01 JP2.2
N$55
  Bottom 0.813: Z-ACHSE.9 81.92,36.83 85.09,40.01
  Bottom 1.27: 85.09,40.01 JP3.2
N$56
  Bottom 0.813: Z-ACHSE.10 79.38,37.47 76.84,40.01 JP4.2
N$57
  Bottom 0.305: 7.62,60.33 Q1.3 8.26,59.69
  Bottom 1.27: 8.26,59.69 8.26,60.33
  Bottom 1.676: 10.16,59.69 R30.2 | 8.26,59.69 10.16,59.69 | 10.16,59.69 R31.2
N$58
  Bottom 1.27: 5.71,65.41 SCHALTAUSGANG.1
  Bottom 1.676: Q1.2 5.71,65.41 10.79,65.41 D14.A
STEP_X
  Bottom 0.813: X-ACHSE.11 20.96,37.47 19.69,38.73 15.24,38.73 14.61,39.37 R28.1 14.61,44.45 15.88,45.72 27.31,45.72 31.75,50.16 OK1.15
STEP_Y
  Bottom 0.813: Y-ACHSE.11 48.89,37.47 47.62,38.73 45.09,38.73 43.81,40.01 | 43.81,40.01 R26.1 | 43.81,40.01 43.81,44.45 47.62,48.26 OK2.11
STEP_Z
  Bottom 0.813: Z-ACHSE.11 76.84,37.47 75.57,38.73 73.03,38.73 71.76,40.01 R24.1 71.76,45.72 67.95,49.53 58.42,49.53 57.78,50.16 OK2.15
VCC  (via drill 0.61)
  Top 0.813: v6.98,44.45 v31.75,44.45 | v33.66,44.45 v51.43,44.45 | v52.7,44.45 v74.3,44.45
  Bottom 0.813: v33.66,44.45 R26.2 | R26.2 33.66,36.83 C2.1 | v52.7,44.45 53.98,43.81 | R24.2 61.59,42.55 60.32,43.81 54.61,43.81 | JP2.1 46.35,43.81 53.98,43.81 | v33.66,44.45 R26.2 | v31.75,44.45 v33.66,44.45 | v33.66,44.45 R26.2 | JP5.1 17.78,42.55 19.05,43.81 26.04,43.81 | 26.04,43.81 30.48,43.81 31.12,44.45 | v33.66,44.45 R26.2 | 26.04,43.81 JP6.1 | 54.61,43.81 JP1.1 | 53.98,43.81 54.61,43.81
  Bottom 1.27: 61.59,36.2 Z-ACHSE.16 | 33.66,36.2 C2.1 | 33.66,36.2 Y-ACHSE.16 | X-ACHSE.16 6.98,36.2 C1.1 | R24.2 R25.2 61.59,36.2 | 61.59,36.2 C3.1 | R26.2 R27.2 33.66,36.2 | R28.2 v6.98,44.45 | IC7.OUT 99.06,33.66 100.33,34.92 C7.1 100.33,40.01 | 100.33,40.01 100.33,50.8 | 100.33,50.8 100.33,60.33 | 100.33,60.33 100.33,69.85 | 100.33,69.85 100.33,80.01 99.97,80.37 ENDSCHALTER.1 | ENDSCHALTER.7 100.13,50.37 100.33,50.8 | ENDSCHALTER.5 100.31,60.35 100.33,60.33 | ENDSCHALTER.3 99.8,70.38 100.33,69.85 | 100.33,40.01 93.34,40.01 88.9,44.45 82.55,44.45 | v31.75,44.45 v33.66,44.45 R26.2 | R26.2 33.66,36.2 | 82.55,44.45 JP3.1 | 82.55,44.45 v74.3,44.45 JP4.1 | 82.55,44.45 82.55,45.09 | OK1.10 19.05,53.34 17.78,54.61 12.06,54.61 R23.2
  Bottom 2.184: v51.43,44.45 v52.7,44.45 | 82.55,45.09 C6.+ | v33.66,44.45 31.12,44.45
  Bottom 2.54: R23.2 v6.98,44.45 R28.2 R29.2 6.98,36.2

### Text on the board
Bottom: Axel Jeromin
